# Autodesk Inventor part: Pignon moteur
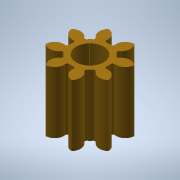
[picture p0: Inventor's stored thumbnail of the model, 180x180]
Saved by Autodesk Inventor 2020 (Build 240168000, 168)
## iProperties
Created: 2002-01
Part Number: Pignon moteur
Material: Laiton (jaune doux)
Document SubType Name: Modélisation
Designer: Philippe
Mass: 0.0204399 g
Surface Area: 0.249071 cm^2
Volume: 0.00241322 cm^3
Density: 8.47 g/cm^3
Appearance: Métal - Laiton
Shininess: 27.0
Angle Display Precision: 2
Document Length Units: 11269
Document Angle Units: 11279
Document Time Units: 11290
Document Mass Units: 11283
Document Length Units Precision: 3
Document Angle Units Precision: 2
Density: 0.0
Volumn: 0.0
Area: 0.0
PropertySet Name: Model Information
Control State: 0
Master: False
Checked Out: False
Author: Philippe
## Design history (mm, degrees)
sketch "Esquisse2"
  geometry: C1 r 0.4 at (0, 0); A1 r 0.55 centre (0, 0) between (0.064, 0.546) and (-0.064, 0.546); A2 r 0.274 centre (-0.39, 0.643) between (-0.119, 0.603) and (-0.379, 0.916); A3 r 0.274 centre (0.39, 0.643) between (0.379, 0.916) and (0.119, 0.603); A4 r 0.05 centre (-0.07, 0.596) between (-0.119, 0.603) and (-0.064, 0.546); A5 r 0.05 centre (0.07, 0.596) between (0.064, 0.546) and (0.119, 0.603); A6 r 0.992 centre (0, 0) between (0.379, 0.916) and (-0.379, 0.916); 1 further point
  constraints: 12 point on circle, 6 centre point, 4 tangent, 2 coincident, 1 equal radius, 4 other
  dimensions: "d9" = 0.8 diameter of C1; "d12" = 1.1 diameter of A1; "d13" = 0.05 radius of A4
extrude "Extrusion1" new body sketch "Esquisse2" distance "d14" = 1.8; taper "d15" = 0 deg
extrude "Extrusion2" cut sketch "Esquisse2" extent not by distance; stored distance "d16" = 1.8; taper "d17" = 0 deg
node "Axe de construction1"
pattern_circular "Réseau circulaire1" dims angle "d20" = 360 deg
node "Solide1"
node "Corps solides"
node "Corps surfaciques"
other parameters: "d1" = 2, "d2" = 1.1
